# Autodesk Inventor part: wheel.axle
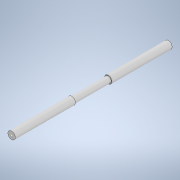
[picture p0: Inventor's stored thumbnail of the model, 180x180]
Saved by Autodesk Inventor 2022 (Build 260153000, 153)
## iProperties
Created: 2021-07
Part Number: wheel.axle
Material: Generic
Document SubType Name: Modeling
Designer: Hp
Density: 1 g/cm^3
Appearance: Default
Author: Hp
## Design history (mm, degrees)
sketch "Sketch1"
  geometry: C1 r 10 at (0, 0); 1 further point
  constraints: 1 centre point, 1 coincident
  dimensions: "d0" = 20 diameter of C1
extrude "Extrusion1" new body sketch "Sketch1" distance "d1" = 122; taper "d2" = 0 deg
sketch "Sketch2"
  geometry: C1 r 10 at (0, 0) reference; C2 r 12.5 at (0, 0); 1 further point
  constraints: 1 centre point, 1 coincident
  dimensions: "d3" = 25 diameter of C2
extrude "Extrusion2" join sketch "Sketch2" distance "d4" = 201.5; taper "d5" = 0 deg
sketch "Sketch3"
  geometry: 1 further point
sketch "Sketch4"
  geometry: C1 r 12.5 at (0, 0); 1 further point
  constraints: 1 centre point, 1 coincident
  dimensions: "d6" = 25 diameter of C1
extrude "Extrusion3" join sketch "Sketch4" distance "d7" = 201.5; taper "d8" = 0 deg
sketch "Sketch7"
  geometry: 1 further point
body "Solid1"
